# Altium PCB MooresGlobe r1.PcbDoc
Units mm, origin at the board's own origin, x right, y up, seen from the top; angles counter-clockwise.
Board outline 12 x 11 mm, 2 copper layers (Top Layer, Bottom Layer), stack 0.801 mm thick; 7 components, 5 nets, 16 pads, 0 vias.
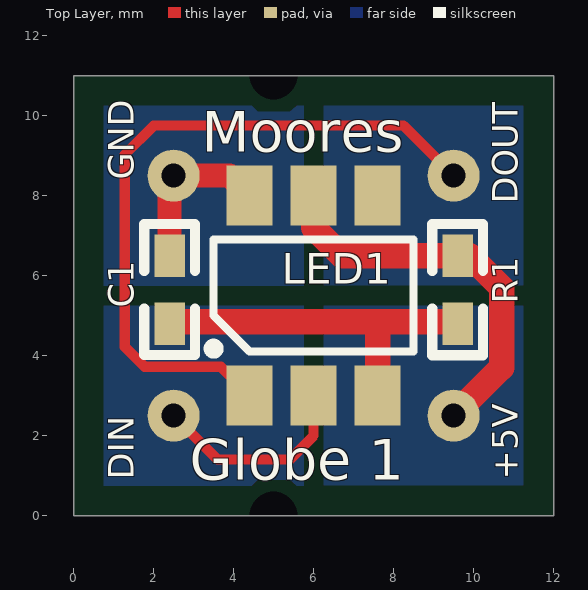
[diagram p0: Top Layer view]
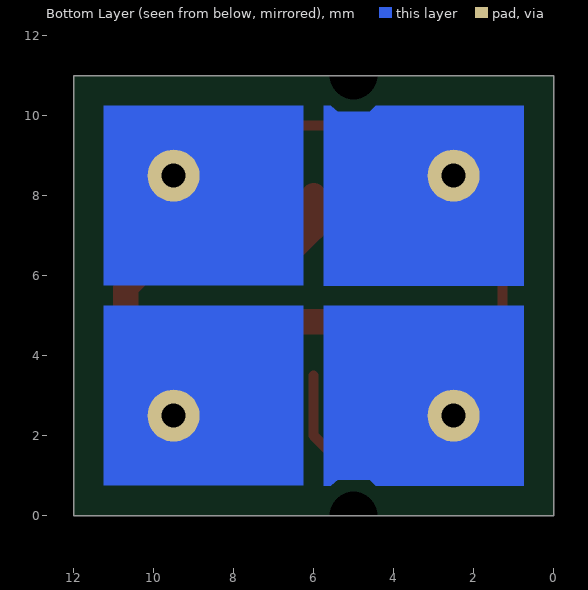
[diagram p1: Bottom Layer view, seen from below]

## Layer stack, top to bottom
Top Layer: signal copper 0.0356
Dielectric: core 0.73, FR-4, Dk 4.8
Bottom Layer: signal copper 0.0356

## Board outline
0,0 12,0 12,11 0,11

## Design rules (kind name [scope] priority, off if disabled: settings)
Clearance [All] p1: gap=0.254
HoleSize [All] p1: absolutevalues=TRUE maxlimit=3 minlimit=0.3 maxpercent=80.000 minpercent=20.000
MinimumSolderMaskSliver [All] p1: minsoldermaskwidth=0.152
PolygonConnect [All] p1: connectstyle=Relief reliefconductorwidth=0.254 reliefentries=4 polygonreliefangle="90 Angle" airgapwidth=0.254
RoutingVias [All] p1: holewidth=0.4 width=0.6 viastyle="Through Hole" minholewidth=0.3 minwidth=0.6 maxholewidth=1 maxwidth=1.27
SilkToSilkClearance [All] p1 off: silktosilkclearance=0
SilkToSolderMaskClearance [IsPad] p1: minsilkscreentomaskgap=0.102 clearancetoexposedcopper=TRUE
SolderMaskExpansion [All] p1: expansion=0.102
Width [All] p1: maxlimit=1.27 minlimit=0.254 preferedwidth=0.254 minimp=50.000000 maximp=50.000000 favimp=50.000000
24 further rules are at their usual default settings.

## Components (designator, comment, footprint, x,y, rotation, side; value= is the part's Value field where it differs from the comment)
+5V "+5V" "Solder Pad"#1 3,10 r90 top
C1 "100n" ARA_0603 2.4,4.8 r90 top
DIN "DIN" "Solder Pad"#2 3,2 r90 top
DOUT "DOUT" "Solder Pad"#3 8.8,10.2 r90 top
GND "GND" "Solder Pad"#4 9,2 r90 top
LED1 "WS2812" PLCC6-IPC 6,5.5 r90 top locked
R1 "100R" ARA_0603 9.6,6.5 r270 top

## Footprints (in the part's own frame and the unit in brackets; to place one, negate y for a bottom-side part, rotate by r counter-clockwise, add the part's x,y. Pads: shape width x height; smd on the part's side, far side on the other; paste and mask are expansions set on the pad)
ARA_0603 [mil]
  rect 42x30 smd: 1(0,0) 2(66.91,0)
  silkscreen extent -31,-25 98,25, body extent 0,-16 67,16, height 20
PLCC6-IPC [mm] "Leaded Chip Carrier, 12-Leads, Body 9.90x5.40mm, Pitch 1.600mm, IPC Medium Density"
  rect 1.5x1.15 smd: 1(-2.5,1.6) 2(-2.5,0) 3(-2.5,-1.6) 4(2.5,-1.6) 5(2.5,0) 6(2.5,1.6)
  silkscreen extent -1.45,-2.5 1.4,2.62, body extent -2.5,-2.5 2.5,2.5, height 1.61
"Solder Pad"#1 [mm]
  round 1.3 hole 0.6 mask-0.25: 1(-7.5,-6.5)
"Solder Pad"#2 [mm]
  round 1.3 hole 0.6 mask-0.25: 1(0.5,0.5)
"Solder Pad"#3 [mm]
  round 1.3 hole 0.6 mask-0.25: 1(-1.7,-0.7)
"Solder Pad"#4 [mm]
  round 1.3 hole 0.6 mask-0.25: 1(6.5,6.5)

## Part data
+5V DIN DOUT GND: library part "Solder Pad", "Solder pad"
C1: library part CAP, "Capacitor Ceramic 100n 50V Y5V 0603"
LED1: "WorldSemi WS2812 Smart RGB LED"
R1: library part "Res Semi", "Resistor 100R 0.1W 5% 0603"

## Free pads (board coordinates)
  round 0 hole 1.2 unplated: 0(5,0) 0(5,11)

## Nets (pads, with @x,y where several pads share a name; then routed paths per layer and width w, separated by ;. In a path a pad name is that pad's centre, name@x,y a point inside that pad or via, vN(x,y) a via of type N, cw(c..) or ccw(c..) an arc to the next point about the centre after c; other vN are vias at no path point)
5V: +5V.1 LED1.5 R1.1 | length 9.8
  Top Layer w0.635: LED1.5 6,7.2 6.7,6.5 9.9,6.5 10.7,5.7 10.7,3.7 +5V.1
DIN: DIN.1 LED1.2 | length 5.7
  Top Layer w0.254: DIN.1 3.6,1.4 5.4,1.4 6,2 LED1.2@6,3.5
DOUT: DOUT.1 LED1.1 | length 17.5
  Top Layer w0.254: LED1.1 3.678,3.722 1.778,3.722 1.278,4.222 1.278,9.028 2,9.75 8.25,9.75 DOUT.1
GND: C1.2 GND.1 LED1.6 | length 4
  Top Layer w0.6: C1.2@2.4,6.8 GND.1@2.4,8.5 ; GND.1 GND.1@2.4,8.5 ; LED1.6 3.9,8.5 GND.1@2.4,8.5
NetC1_1: C1.1 LED1.3 R1.2 | length 8.6
  Top Layer w0.635: C1.1@2.4,4.85 7.6,4.85 ; LED1.3@7.6,3.5 7.6,4.85 ; R1.2@9.6,4.85 7.6,4.85
pads on no net: LED1.4

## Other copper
Bottom Layer:
  rectangle net DOUT: 6.25,5.75 11.25,10.25
  rectangle net 5V: 6.25,0.75 11.25,5.25
  region net DIN: 0.75,5.25 5.75,5.25 5.75,0.75 5.575,0.75 5.4,0.9 4.6,0.9 4.45,0.75 0.75,0.75
  region net GND: 0.75,5.75 5.75,5.75 5.75,10.25 5.575,10.25 5.4,10.1 4.6,10.1 4.45,10.25 0.75,10.25

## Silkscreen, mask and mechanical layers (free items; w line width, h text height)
Top Overlay:
  text "Moores" at 3.2,9.1 h1.02
  text "Globe 1" at 2.9,0.9 h1.02
Mechanical 1:
  the board outline again, w0.6
Mechanical 2:
  rectangle: 4.3,0 5.7,1.4
  rectangle: 5.3,9.6 6.7,11
  region: 0,11 0,10.4 2.2,11
  region: 0,0 0,0.6 2.2,0
  region: 12,0 12,0.6 9.8,0
  region: 12,11 12,10.4 9.8,11
  text "Top Layer Component Keep Out Areas" at 21,4 h1
Mechanical 3:
  rectangle: 9.5,0 12,0.7
  rectangle: 0,0 2.5,0.75
  rectangle: 0,10.25 2.5,11
  rectangle: 9.5,10.3 12,11
  rectangle: 5.25,10.25 6.75,11
  rectangle: 5.25,0 6.75,0.75
  text "Bottom Layer Component Keep Out Areas" at 21,2 h1
Drill Drawing:
  lines w0.1: 21,-3.25 79.25,-3.25 ; 21,-1.25 79.25,-1.25 ; 21,7.5 79.25,7.5 ; 21,9.5 79.25,9.5 ; 21,11.5 79.25,11.5 ; 21,13.5 79.25,13.5 ; 21,15.5 79.25,15.5 ; 21,17.5 79.25,17.5 ; 21,19.5 79.25,19.5 ; 21,21.5 79.25,21.5 ; 33.5,-5.25 33.5,1 ; 33.5,5.5 33.5,23.5 ; 0,0 12,0 12,11 0,11 0,0 ; 21,-5.25 79.25,-5.25 79.25,1 21,1 21,-5.25 ; 21,5.5 21,23.5 79.25,23.5 79.25,5.5 21,5.5
  text ".legend" at 22.25,28.75 h1
  text "BOARD SIZE:" at 21.5,22 h1
  text "12.00mm x 11.00mm" at 34.5,22 h1
  text "LAYERS:" at 21.5,20 h1
  text "2" at 34.5,20 h1
  text "MATERIAL:" at 21.5,18 h1
  text "FR4 0.8mm" at 34.5,18 h1
  text "COPPER:" at 21.5,16 h1
  text "35um (after plating)" at 34.5,16 h1
  text "PTH PLATING:" at 21.5,14 h1
  text "20um (minimum)" at 34.5,14 h1
  text "FINISH:" at 21.5,12 h1
  text "ROHS HAL" at 34.5,12 h1
  text "OVERLAY:" at 21.5,10 h1
  text "Black, 1 side" at 34.5,10 h1
  text "SOLDER MASK:" at 21.5,8 h1
  text "White, 2 sides" at 34.5,8 h1
  text "PROFILING:" at 21.5,6 h1
  text "V-Groove" at 34.5,6 h1
  text "FILE NAME:" at 21.5,-0.75 h1
  text ".Pcb_File_Name_No_Path" at 34.5,-0.75 h1
  text "LAYER:" at 21.5,-2.75 h1
  text ".Plot_File_Name" at 34.5,-2.75 h1
  text "PRINT DATE:" at 21.5,-4.75 h1
  text ".Print_Date" at 34.5,-4.75 h1
Mechanical 20:
  the board outline again, w0.1

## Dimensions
-1,0 to -1,11 on Mechanical 16
0,-1 to 12,-1 on Mechanical 16
6.25,13 to 5.75,13 on Mechanical 16
13,0 to 13,0.75 on Mechanical 16
0,0 to 12,0 on Drill Drawing
0,0 to 0,11 on Drill Drawing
